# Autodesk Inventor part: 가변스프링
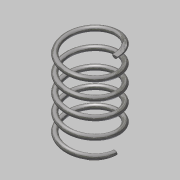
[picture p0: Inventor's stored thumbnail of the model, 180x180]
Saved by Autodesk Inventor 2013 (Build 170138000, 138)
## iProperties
Created: 2019-05
Part Number: 가변스프링
Material: 스테인리스강
Document SubType Name: Modeling
Designer: Administrator
Density: 8.08 g/cm^3
Mass: 7.87511 g
Surface Area: 19.7325 cm^2
Volume: 0.974642 cm^3
Author: Administrator
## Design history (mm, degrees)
sketch "스케치1"
  geometry: L1 (0, 0)-(10, 0); L2 (10, 0)-(10, 34); L3 (10, 34)-(0, 34); L4 (0, 34)-(0, 0); C1 r 1 at (10, 0)
  constraints: 8 end point, 2 parallel, 1 centre point, 1 coincident, 1 horizontal, 1 perpendicular
  dimensions: "d0" = 2 diameter of C1; "d1" = 20 diameter of L2 L4; "d2" = 34 distance of L1.end L2.end (derived)
feature "코일1" sketch "스케치1" pitch "d3" = 10; turns "d5" = 5; dims "d4" = 34 (= d2), "d6" = 0, angle "d7" = 90 deg, angle "d8" = 90 deg, "d9" = 0, "d10" = 0
sketch "스케치3"
  geometry: L1 (34, 12)-(0, 12); L2 (0, 12)-(0, -12); L3 (0, -12)-(34, -12); L4 (34, -12)-(34, 12); 2 further points
  constraints: 8 end point, 2 parallel, 1 coincident, 1 horizontal, 1 midpoint, 1 perpendicular
  dimensions: "d11" = 34 distance of L2.end L3.end (derived); "d13" = 24 distance of L3.end L1.start
extrude "돌출1" sketch "스케치3" stored distance "d14" = 24; taper "d15" = 0 deg
node "솔리드1"
